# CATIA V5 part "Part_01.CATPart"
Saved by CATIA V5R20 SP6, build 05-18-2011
Part number: Part_01
Bounding box of the stored display mesh (mm): x -6 to 15, y 0 to 4.8, z -6 to 44
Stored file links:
  E:\#01 CATIA Lecture Materials\#16 3D Print Test\3D Print Test\17th Test\Part_01.CATPart
  E:\#01 CATIA Lecture Materials\#16 3D Print Test\3D Print Test\17th Test\Part_02.CATPart
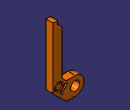
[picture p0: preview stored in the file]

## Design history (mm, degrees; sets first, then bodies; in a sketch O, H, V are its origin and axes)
Set1 "Reference Data"
  Point1 "Center Point": (0, 0, 0)
Body1 (main body)
  Sketch1 on zx-plane, origin (0, 0, 0), H (-1, 0, 0), V (0, 0, 1)
    circle A1 centre (0, 0) radius 3.1
    arc A2 centre (0, 0) radius 6 from (0, -6) to (0, 6) ccw
    point P1 (0, 6)
    line L1 (0, 6) -> (-9, 6)
    line L2 (-9, 6) -> (-9, 39)
    point P3 (-9, 39)
    line L3 (-9, 39) -> (-12, 42)
    point P4 (-12, 42)
    line L4 (-12, 42) -> (-12, 44)
    line L5 (-12, 44) -> (-15, 44)
    line L6 (-15, 44) -> (-15, 3)
    line L7 (-15, 3) -> (-6, -6)
    point P8 (-6, -6)
    line L8 (-6, -6) -> (0, -6)
    distance L8 L1 = 12
    distance L8 L5 = 50
    distance L5 P4 = 2
    distance L5 P3 = 5
    distance L6 L4 = 3
    distance L6 L2 = 6
    angle L8 L7 = 45
    distance V P8 = 6
    distance L6 V = 15
    radius A1 = 3.1
    coincidence: P1 V
    tangency: L1 A2, L8 A2
    vertical: L2 V, L4 V, L6 V
    horizontal: L5 H, L8 H, L1 H
  Pad1: profile Sketch1, direction (0, 1, 0), length 4.8
  Chamfer1: length 3, angle 45, on edge [face of Pad1 from Sketch1.L2 | face of Pad1 from Sketch1.L1]
  Sketch2 on end face of Pad1, origin (0, 4.8, 0), H (-1, 0, 0), V (0, 0, 1)
    polyline C1
    point P2 (-6.2233, 3.9749)
    polyline C2
    polyline C3
    point P5 (-6.2233, 3.9749)
    polyline C4
    coincidence: P2 P5
  Pocket1: profile Sketch2, direction (0, -1, 0), length 1, thin wall 1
